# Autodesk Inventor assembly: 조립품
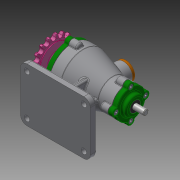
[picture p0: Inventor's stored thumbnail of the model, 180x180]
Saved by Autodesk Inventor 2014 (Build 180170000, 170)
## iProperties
Created: 2020-12
Part Number: 조립품
Document SubType Name: Assembly
Designer: kh
Author: kh
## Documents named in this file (15)
- C:\Users\kh\Desktop\701206V1026\조립품.iam
- C:\Users\kh\Desktop\701206V1026\본체.ipt
- C:\Users\kh\Desktop\701206V1026\개스킷 A.ipt
- C:\Users\kh\Desktop\701206V1026\개스킷 B.ipt
- C:\Users\kh\Desktop\701206V1026\뒤커버.ipt
- C:\Users\kh\Desktop\701206V1026\마개.ipt
- C:\Users\kh\Desktop\701206V1026\베어링 6200.ipt
- C:\Users\kh\Desktop\701206V1026\베어링 6203.ipt
- C:\Users\kh\Desktop\701206V1026\볼트 M5.ipt
- C:\Users\kh\Desktop\701206V1026\스프로킷.ipt
- C:\Users\kh\Desktop\701206V1026\앞커버.ipt
- C:\Users\kh\Desktop\701206V1026\오일 실 10 20 7.ipt
- C:\Users\kh\Desktop\701206V1026\오일 실 17 30 8.ipt
- C:\Users\kh\Desktop\701206V1026\축.ipt
- C:\Users\kh\Desktop\701206V1026\키 4x4x14.ipt
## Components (2 placed, 2 different names)
1. 개스킷 A:1
2. 개스킷 B:1
